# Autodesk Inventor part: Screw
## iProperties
Shininess: 12.0
Length Units: 11272
Angle Units: 11279
Time Units: 11290
Mass Units: 11283
Length Display Precision: 2
Angle Display Precision: 1
Created: 1999-05
Part Number: Screw
Document SubType Name: Modeling
Designer: Administrator
Density: 8.94 g/cm^3
Density: 8.94
Volumn: 11.91003151861203
Area: 51.879342766234146
PropertySet Name: Model Information
Control State: 0
Master: False
Checked Out: False
Author: Administrator
